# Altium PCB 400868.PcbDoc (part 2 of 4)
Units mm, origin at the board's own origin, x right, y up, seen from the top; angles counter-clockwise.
Board outline 117 x 63.5 mm, 4 copper layers (Top Layer, Mid-Layer 1, Mid-Layer 2, Bottom Layer), stack 1.58 mm thick; 211 components, 153 nets, 878 pads, 1351 vias.
Unrouted connection lines stored in the file: 16.
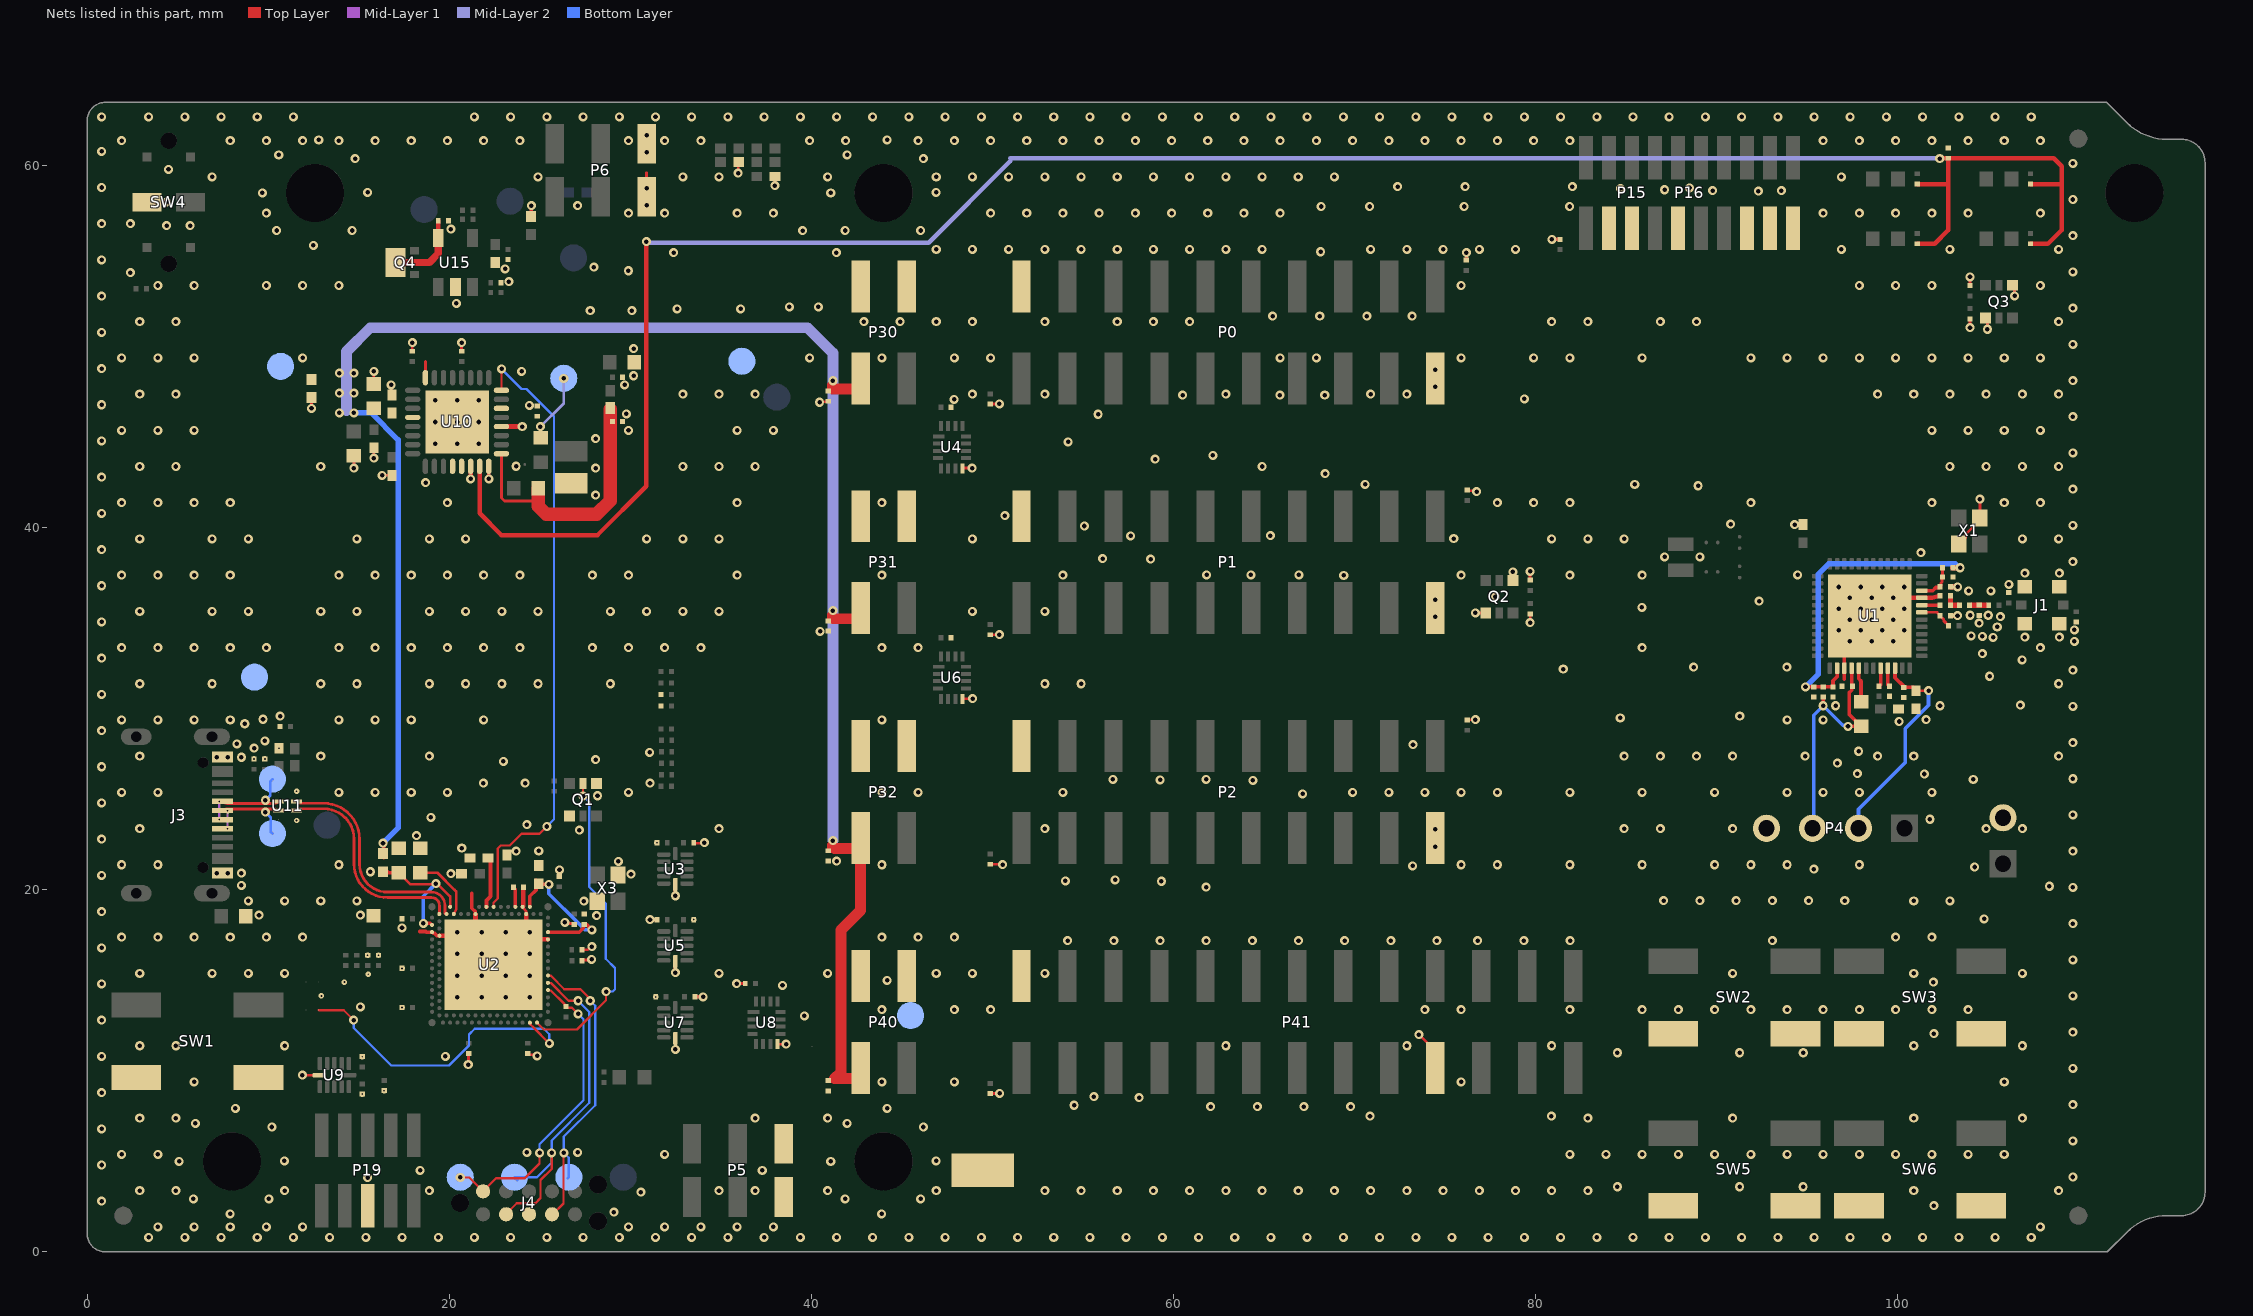
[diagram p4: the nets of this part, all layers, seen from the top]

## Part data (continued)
C10 C14: library part C0201-2µ2-2.5V-X6T-GRM033D80E225ME47D, "Capacitor, Ceramic, 2.2µF 2.5V X6T 0201,±20%", Manufacturer=Murata, Manufacturer Part Number=GRM033D80E225ME47D, Part number IPS=N.A., Part number NEMS=100200527, Supplier Part Number 1=81-GRM033D80E225ME7D
C11: library part C0201-10n-6.3V-X7R, "Capacitor, X7R, 6.3V", Manufacturer=Murata, Manufacturer Part Number=GRM033R70J103KA01D, Part number IPS=N.A., Part number NEMS=100200407, Supplier Part Number 1=490-1262-1-ND
C12: library part C0201-1n0, "Capacitor, X7R, ±10%, 25V", Manufacturer=N.A., Part number IPS=00000003206, Part number NEMS=100200056
C13: library part C0201-3.9p, "Chip Cap 0201", Manufacturer=N.A., Part number NEMS=100200024,100200424
C15 C16 C17 C18 C19 C20 C21 C22 C25 C29 C34 C35 C36 C37 C44 C46 C48 C51 C52 C53 C55 C56 C57 C60 C61 C62 C63 C64 C65 C66 C67 C68 C69 C70 C71 C72 C74 C77 C78 C79 C80 C82: library part C0201-100n, "Capacitor, X5R, ±10%", Manufacturer=N.A., Part number IPS="00000001248, 00000002505", Part number NEMS=100200078, Part number Norautron=262071862
C23: library part C0402-2µ2-10V, "Capacitor, X5R, ±10%", Manufacturer=N.A., Part number NEMS=100200376, Supplier Part Number 1=490-10451-1-ND
C24 C26 C27: library part C0603-10µ-10V-X7T-GRM188D71A106MA73, "Capacitor, X7T, ±20%, 10V", Manufacturer=Murata, Manufacturer Part Number=GRM188D71A106MA73D, Part number IPS=00000004696, Part number NEMS=100200414, Part number Norautron=N.A., Supplier Part Number 1=490-7200-1-ND
C30 C87: library part C0201-10n, "Capacitor, X7R, ±10%", Manufacturer=N.A., Part number IPS=00000003480, Part number NEMS=100200067, Part number Norautron=26621779
C31 C32 C38 C39 C45 C75 C81: library part C0402-1µ0-6.3V-X5R-10%, "Capacitor, X5R, ±10%, 6.3V", Manufacturer=N.A., Part number NEMS=100200498, Part number Norautron=26207137
C33: library part C0201-2n2, "Capacitor, X7R, ±10%, 10V", Manufacturer=N.A., Part number IPS=00000001778, Part number NEMS=100200060, Part number Norautron=26470002
C40: library part C0603-2µ2-6.3V-X7R, "Capacitor, X7R, ±10%, 6.3V", Manufacturer=N.A., Part number NEMS=100200272
C41: library part C0402-100n, "Capacitor, X7R, ±10%", Manufacturer=N.A., Part number IPS=00000005296, Part number NEMS=100200184
C42 C43 C54 C58: library part C0603-4µ7-10V-X7S, "Capacitor, X7S, ±10%, 10V", Manufacturer=N.A., Part number IPS=00000001779, Part number NEMS=100200351, Supplier Part Number 1=445-14258-1-ND
C47: library part C0402-1µ0-16V-X5R, "Capacitor, Ceramic, X5R, ±10%, 16V", Manufacturer=Murata, Manufacturer Part Number=GRT155R61C105KE01D, Part number IPS=N.A., Part number NEMS=100200452, Supplier Part Number 1=490-12255-1-ND
C59: library part C0603-10n-100V-X7R, "Capacitor, X7R, ±10%, 100V", Manufacturer=Murata, Manufacturer Part Number=GCM188R72A103KA37D, Part number IPS=N.A., Part number NEMS=100200349, Supplier Part Number 1=490-4781-1-ND
C73: library part C0201-1p8-50V-COG-GJM0335C1H1R8BB01, "CAP CER 1.8PF 50V C0G/NP0 0201", Manufacturer=Murata, Manufacturer Part Number=GJM0335C1H1R8BB01, Part number IPS=N.A., Part number NEMS=100200681, Supplier Part Number 1=490-17159-1-ND
C76: library part C0402-1µ0-10V-X5R, "Capacitor, Ceramic, X5R, ±10%, 10V", Manufacturer=N.A., Part number NEMS=100200482
FB1 FB2: library part FB0201-120R@100M-200mA-BLM03AG121SN1D, "Ferrite Bead, 120 Ohm @ 100MHz, 200mA, 500 mOhm Max", Manufacturer=Murata, Manufacturer Part Number=BLM03AG121SN1D, Part number IPS=N.A., Part number NEMS=100300419, Supplier Part Number 1=490-5622-1-ND
FB3 FB4: library part FB0402-120R@100M-500mA, "Ferrite Bead, 120 Ohm @ 100MHz, 500mA, 250 mOhm Max", Manufacturer=Murata, Manufacturer Part Number=BLM15AG121SN1D, Part number IPS=00000009954, Part number NEMS=100300099, Part number Norautron=265230631, Supplier Part Number 1=490-1005-1-ND
Fid1 Fid2 Fid3: library part Fid-Mark, "Fiducial Mark", Manufacturer=N.A., Part number NEMS=100500073
J1: "Coaxial Connector with Switch", Manufacturer=Murata, Part number IPS=00000009955, Part number NEMS=100500400, Part number Norautron=26030338, Supplier Part Number 1=490-4981-1-ND
J3: library part 80259-1021, "USB-C Receptacle, 16 Pin, USB 2.0", Manufacturer="Bellweather Electronic Corp.", Part number IPS=N.A., Part number NEMS=100500830
J4: library part TC2050-IDC-NLFP, "CBL PLUG-OF-NAILS 10-PIN", Manufacturer="Tag-Connect LLC", Part number IPS=N.A., Part number NEMS=100500463, Supplier Part Number 1=TC2050-IDC-NL-ND
JP1: library part "SHUNT JUMPER 2.54mm Black Vertical", "Shunt Jumper 2.54mm Black, open top", Manufacturer=WCON, Manufacturer Part Number=3710-6001OS0B05, Part number IPS=N.A., Part number NEMS=100500728
L1: library part L0603-4µ7-MLZ1608M4R7WT000, "Inductor, 120mA, ±20%, 0.65R", Manufacturer="TDK Corporation", Manufacturer Part Number=MLZ1608M4R7WT000, Part number IPS=N.A., Part number NEMS=100300440, Supplier Part Number 1=445-6390-2-ND
L2: library part L0201-2n7-HQ-Murata, "Inductor, 600mA, ±0.1ｎH, 120mOhm", Manufacturer=Murata, Manufacturer Part Number=LQP03HQ2N7B02, Part number IPS=00000001753, Part number NEMS=100300214, Part number Norautron=N.A., Supplier Part Number 1=490-13909-1-ND
L3 L4: library part L0201-3n5-HQ-Murata, "Inductor, 500mA, ±0.1ｎH, 170mOhm", Manufacturer=Murata, Manufacturer Part Number=LQP03HQ3N5B02, Part number IPS=N.A., Part number NEMS=100300222, Supplier Part Number 1=490-13925-1-ND
L8: library part L0806-2µ2-2500mA-73mOhm-CIGT201610EH2R2MNE, "Inductor, Irms=2.5A, Isat=2.9A, ±20%, DCR=73mΩ", Manufacturer="Samsung Electro-Mechanics America", Manufacturer Part Number=CIGT201610EH2R2MNE, Part number IPS=N.A., Part number NEMS=100300400, Part number Norautron=26521789, Supplier Part Number 1=1276-6901-1-ND
LABEL1: library part Label_12x12, "PCA version label, stick-on, 12x12mm", Manufacturer="Ellco Etikett", Manufacturer Part Number=A33512‐01, Part number IPS=N.A., Part number NEMS=101200028
LABEL2: library part Label_20x40, "Early Access Label", Manufacturer=NA, Part number IPS=N.A.
LD1 LD2 LD3 LD4 LD5: library part "VS 25C7M5", "LED, Green, 0603, 573nm, Vf=2.0V, 24mcd, - 40 to +85°C", Manufacturer="Victory Electronics", Part number IPS="00000001274, 00000009961", Part number NEMS=101400097, Part number Norautron=26313411, Supplier Part Number 1=N.A.
LOGO1: library part "Nordic Logo lying", "Nordic logo lying", Manufacturer=N.A., Part number NEMS=101100001
LOGO2: library part "WEEE Symbol 3x4.5mm", "WEEE Directive symbol", Manufacturer=N.A., Part number NEMS=101100006
LOGO3: "Segger logo, small size", Manufacturer=N.A., Part number NEMS=101100004
NT2: library part "2 pin starpoint", "Starpoint", Manufacturer=N.A., Part number NEMS=100500603
P0 P1 P2: library part "Pin Header 2x10 SMD, 2.54mm", "Pin Header 2x10, 2.54mm (100mil) SMD", Manufacturer=WCON, Manufacturer Part Number=1125-1210S0M116CR09, Part number IPS=N.A., Part number NEMS=100500738
P3: "Pin List 1x2, 2.54mm (100mil)", Manufacturer=N.A., Part number NEMS=100500297
P4: "Pin List 1x4, 2.54mm (100mil)", Manufacturer=N.A., Part number NEMS=100500309
P5 P6: library part "Pin List 1x3 SMD", "Pin List 1x3, 2.54mm (100mil), SMD", Manufacturer=WCON, Manufacturer Part Number=1125-1103S0M116CR04, Part number IPS=N.A., Part number NEMS=100500306, Part number Norautron=26470016
P15 P19: library part "Pin Header 2x5 SMD, 1.27mm, KS", "Pin Header 2x5, 1.27mm (50mil), SMD, Keying Shroud", Manufacturer=WCON, Manufacturer Part Number=3132-10MS0BK00R5, Part number IPS=N.A., Part number NEMS=100500261
P16: library part "Pin Header 2x10 SMD, 1.27mm, KS, N.C.", "Pin Header 2x10, 1.27mm (50mil), SMD, Keying Shroud", Manufacturer=WCON, Manufacturer Part Number=3132-20MS0BK00R1, Part number IPS=N.A., Part number NEMS=100500279
P30 P31 P32 P40: "Pin Header 2x2, SMD, 2.54mm (100mil)", Manufacturer=WCON, Manufacturer Part Number=1125-1202S0M116CR03, Part number IPS=N.A., Part number NEMS=100500770
P41: library part "Pin Header 2x13 SMD, 2.54mm", "Pin Header 2x13, 2.54mm (100mil) SMD", Manufacturer=WCON, Manufacturer Part Number=1125-1213S0M116CR09, Part number IPS=N.A., Part number NEMS=100500908
Q1 Q2 Q3: "MOSFET 2N-CH 60V 0.17A TSSOP6 (SOT363)", Manufacturer=Nexperia, Manufacturer Part Number=NX138AKSX, Part number IPS=N.A., Part number NEMS=101300207, Supplier Part Number 1=1727-2732-2-ND
Q4: library part PBSS4330PA,115, "30V, 3A, 2.1W, G=270, NPN Transistor", Manufacturer=Nexperia, Part number IPS=N.A., Part number NEMS=101300184, Supplier Part Number 1=1727-5112-1-ND‎
R1 R36: library part R0201-1k0, "Resistor, ±1%, 0.05W", Manufacturer=N.A., Part number IPS=00000005786, Part number NEMS=100100043
R2: library part R0402-1R0, "Resistor, ±1%, 0.063W", Manufacturer=N.A., Part number IPS=00000004795, Part number NEMS=100100112, Part number Norautron=261080032
R5: library part R0201-560, "Resistor, ±1%, 0.05W", Manufacturer=N.A., Part number IPS=00000007447, Part number NEMS=100100038
R6 R8 R13 R14 R15 R16 R17 R23 R28 R29 R32 R39 R56: library part R0201-100k, "Resistor, ±1%, 0.05W", Manufacturer=N.A., Part number IPS=00000001419, Part number NEMS=100100080, Part number Norautron=26108487
R7: library part R0201-47R, "Resistor, ±1%, 0.05W", Manufacturer=N.A., Part number IPS=00000004794, Part number NEMS=100100022, Part number Norautron=26108300
R10 R11 R12 R18 R27: library part R0201-1M0, "Resistor, ±1%, 0.05W", Manufacturer=N.A., Part number IPS=00000001418, Part number NEMS=100100093, Part number Norautron=26107108
R19 R20 R21 R22: library part R0201-220, "Resistor, ±1%, 0.05W", Manufacturer=N.A., Part number IPS=00000000863, Part number NEMS=100100032, Part number Norautron=26107014
R25 R26 R35: library part R0201-0R, "Resistor, ±5%, 0.05W", Manufacturer=N.A., Part number IPS=00000003245, Part number NEMS=100100001
R40: library part R0402-2R2, "Resistor, ±1%, 0.063W", Manufacturer=N.A., Part number IPS=00000001796, Part number NEMS=100100116, Part number Norautron=26470034
R46 R47: library part R0201-10k, "Resistor, ±1%, 0.05W", Manufacturer=N.A., Part number IPS=00000001255, Part number NEMS=100100065, Part number Norautron=26107101
R48: library part R0201-33k, "Resistor, ±1%, 0.05W", Manufacturer=N.A., Part number IPS=00000001708, Part number NEMS=100100073
R50 R51 R52 R53: library part R0402-0R, "Resistor, ±5%, 0.063W", Manufacturer=N.A., Part number IPS=00000007128, Part number NEMS=100100109, Supplier Part Number 1=146-9661
R54 R55: library part R0402-10k, "Resistor, ±1%, 0.063W", Manufacturer=N.A., Part number IPS=00000002093, Part number NEMS=100100198, Supplier Part Number 1=173-8864
SB1 SB8: Manufacturer=N.A., Part number NEMS=100500458
SB2: library part "Solderbridge Shorted", "Shorted Solderbridge", Manufacturer=N.A., Part number NEMS=100500459
SB3 SB4: library part "Solderbridge Shorted 0.4mm", "Shorted Solderbridge", Manufacturer=N.A., Part number NEMS=100500561
SB5 SB6: library part "Solderbridge 0.4mm", Manufacturer=N.A., Part number NEMS=100500560
SW1 SW2 SW3 SW5 SW6: library part Switch-PB-6.2x6.3mm-SMD, "Tactile Switch, SPNO, SMD, 160gf, 6.2x6.3x2.5mm", Manufacturer=Dailywell, Manufacturer Part Number=TS604VM1-025BR-R, Part number IPS=00000007812, Part number NEMS="101500001, 101500133", Part number Norautron=N.A.
SW4: library part Switch-Slide-RA-J-Lead-DPDT-8.5x3.5mm_C&K, "SMD slide Switch (ON-ON)", Manufacturer=C&K, Manufacturer Part Number=JS202011JAQN, Part number IPS=00000007811, Part number NEMS=101500037, Part number Norautron=N.A., Supplier Part Number 1=CKN10722CT-ND
TP1 TP3 TP4 TP5 TP6 TP8 TP9 TP10 TP11 TP12 TP13 TP14 TP15 TP16 TP17 TP18: library part TP_SMD_Ø1.5MM, "1.5mm circular SMD testpad", Manufacturer="Nordic Semiconductor", Manufacturer Part Number=N.A., Part number NEMS=100500477
TP22: library part "TP - S1751-46R", "PC TEST POINT TIN SMD L", Manufacturer=Harwin, Manufacturer Part Number=S1751-46R, Part number IPS=N.A., Part number NEMS=100500525, Supplier Part Number 1=952-1478-1-ND
U1: "Multi-protocol Bluetooth Low Energy, IEEE 802.15.4 and 2.4GHz proprietary Wireless MCU", Manufacturer="Nordic Semiconductor", Part number IPS=N.A., Part number NEMS=102000385
U2: "Multi-protocol Bluetooth Low Energy, IEEE 802.15.4, ANT and 2.4GHz proprietary system-on-chip", Manufacturer="Nordic Semiconductor", Part number IPS=N.A., Part number NEMS=102000153
U3 U5: library part TXU0204RUTR, "4-Bit Fixed Direction Voltage-Level Translator with Schmitt-Trigger Inputs and 3-State Outputs", Manufacturer="Texas Instruments", Part number IPS=N.A., Part number NEMS=101900849, Supplier Part Number 1=296-TXU0204RUTR-ND
U4 U6 U8: "Low-Capacitance, 1:1 (SPST) 4-Channel, analog switch", Manufacturer="Texas Instruments", Manufacturer Part Number=TMUX1511RSVR, Part number IPS=N.A., Part number NEMS=101900847, Supplier Part Number 1=296-53443-2-ND
U7: library part TXB0304RUTR, "4-Bit Bidirectional Level-Shifter/Voltage Translator with Automatic Direction Sensing", Manufacturer="Texas Instruments", Part number IPS=N.A., Part number NEMS=101900199, Supplier Part Number 1=296-29682-1-ND
U9: library part TXB0104RUTR, "4-Bit Bidirectional Level-Shifter/Voltage Translator with Automatic Direction Sensing", Manufacturer="Texas Instruments", Part number IPS=N.A., Part number NEMS=101900856, Supplier Part Number 1=296-25888-2-ND
U10: "Li-Ion/Li-Polymer USB-C battery charger with high efficiency buck regulators, LDOs or load switches, LED drivers, TWI and VBUSOUT", Manufacturer="Nordic Semiconductor", Part number IPS=N.A., Part number NEMS=102000291
U11: "2 Line Common mode filter with ESD protection for USB 2.0 interface", Manufacturer=STMicroelectronics, Part number IPS=N.A., Part number NEMS=100800034, Supplier Part Number 1=497-13420-2-ND
U15: library part TLV271CW5-7, "Dual rail to rail CMOS Amplifier", Manufacturer="Diodes Incorporated", Part number IPS=N.A., Part number NEMS=101900398, Supplier Part Number 1=TLV271CW5-7DICT-ND
X1: library part XTAL_SMD2016_32MHz_8pF_Kyocera, "XTAL SMD 2016, 32MHz, Cl=8pF, Tot: ±40ppm", Manufacturer=Kyocera, Manufacturer Part Number=CX2016DB32000D0WZRC1, Part number IPS=00000007827, Part number NEMS=101600039, Part number Norautron=26511136, Supplier Part Number 1=1253-1586-1-ND
X2: library part XTAL_SMD2012_32.768kHz_9pF_TXC, "XTAL SMD 2012, 32.768kHz, 9pF, ±20ppm", Manufacturer="TXC Corporation", Manufacturer Part Number=9HT11-32.768KDZC-T, Part number IPS=N.A., Part number NEMS=101600107, Supplier Part Number 1=887-1426-2-ND
X3: library part XTAL_SMD2016_32MHz_8pF_Golledge, "XTAL SMD 2016, 32MHz, Cl=8pF, Tol: ±10ppm, Stab: ±15ppm", Manufacturer=Golledge, Manufacturer Part Number=MP06003, Part number IPS=00000001431, Part number NEMS=101600041,101600118, Part number Norautron=N.A.

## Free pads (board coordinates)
  round 3.2 hole 3.2 unplated: 1(8.004,5) 1(12.604,58.5) 1(44.004,5) 1(44.004,58.5) 1(113.104,58.5)

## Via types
v1: diameter 0.5, hole 0.25, Top Layer to Bottom Layer, tented both sides, 1252 vias
v2: diameter 0.3, hole 0.1, Top Layer to Mid-Layer 1, tented top, 72 vias
v3: diameter 0.3, hole 0.1, Top Layer to Mid-Layer 1, tented both sides, 18 vias
v4: diameter 0.5, hole 0.25, Top Layer to Bottom Layer, tented bottom, 9 vias

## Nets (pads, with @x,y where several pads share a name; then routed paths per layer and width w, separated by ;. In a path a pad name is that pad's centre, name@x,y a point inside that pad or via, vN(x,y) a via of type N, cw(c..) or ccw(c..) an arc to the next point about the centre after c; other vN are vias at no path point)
5V0: C24.2 C26.2 C55.2 C56.2 C60.2 C63.2 C74.2 C75.2 C78.1 P30.1 P31.1 P32.1 P40.1 Q4.3 R40.2 R55.2 TP10.1 U10.4 U10.20 U10.30 U10.32 U15.5 | length 120.3
  Top Layer w0.15: U10.32@22.192,43.396 U10.32@22.196,43.392 ; v1@22.196,42.704 v1(22.2,42.7)
  Top Layer w0.2: v1(16.35,22.587) 16.392,22.545 R40.2@16.392,21.787 ; v1@22.196,42.704 U10.32@22.196,43.392 ; C63.2@40.95,22.16 C63.2@40.965,22.16 ; C60.2@40.965,34.86 40.965,35.19 v1(41.2,35.425) ; C55.2@40.965,47.56 40.965,47.89 v1(41.2,48.125) ; 41.143,22.353 41,22.21 41,22.195 C63.2@40.965,22.16 ; v1(41.2,22.725) 40.965,22.49 C63.2@40.965,22.16
  Top Layer w0.25: v1(21.192,42.7) U10.30@21.192,43.396
  Top Layer w0.27: U15.5@19.4,56 C78.1@19.4,56.975 ; C74.2@40.95,9.46 P40.1@42.361,9.46 ; C63.2@40.95,22.16 P32.1@42.361,22.16 ; P31.1@42.734,34.663 P31.1@42.734,35.56 ; P30.1@42.75,46.99 P30.1@42.75,47.75
  Top Layer w0.3: U10.4@22.892,45.596 v1@24.038,45.596
  Top Layer w0.4: Q4.3@17.05,54.65 18.9,54.65 19.4,55.15 U15.5@19.4,56
  Top Layer w0.6: 41.225,34.975 P31.1@42.6,34.975 ; 41.225,47.675 P30.1@42.6,47.675 ; 41.299,22.275 P32.1@42.6,22.275 ; P40.1@42.6,9.575 41.299,9.575 41.65,9.926 41.65,17.775 42.734,18.859 42.734,22.368 P32.1@42.759,22.393
  Mid-Layer 2 w0.15: v1(25.042,45.596) 25.061,45.596 26.334,46.869 v1(26.334,48.26)
  Mid-Layer 2 w0.6: 14.342,46.479 14.342,49.746 15.646,51.05 39.8,51.05 41.2,49.65 v1(41.2,48.125) v1(41.2,35.425) v1(41.2,22.725)
  Bottom Layer w0.3: v1(14.742,46.346) 15.704,46.346 17.192,44.858 17.192,23.429 v1(16.35,22.587)
  other v1: 24.042,45.596 13.942,46.346 13.942,47.446 14.742,47.446 13.942,48.546 14.742,48.546
ANT: L2.1 U1.32 | length 0.9
  Top Layer w0.2: U1.32@101.505,35.73 L2.1@102.364,35.73
CFLYH: C3.2 U1.21 | length 0.9
  Top Layer w0.125: C3.2@99.565,31.222 C3.2@99.565,31.237
  Top Layer w0.2: U1.21@99.48,32.105 99.48,31.34 C3.2@99.565,31.255
CFLYL: C3.1 U1.20 | length 1
  Top Layer w0.125: C3.1@99.004,31.237 99.004,31.214 C3.1@99.068,31.15
  Top Layer w0.2: C3.1@98.995,31.24 98.995,31.255 99.08,31.34 U1.20@99.08,32.105
D_N: J3.A7 J3.B7 TP17.1 U11.2 | length 5.5
  Top Layer w0.153: J3.B7@7.489,24.875 ccw(c7.727,25.113) 7.727,24.777 10.322,24.777 ccw(c10.322,25.141) U11.2@10.579,24.883
  Mid-Layer 1 w0.127: v2(7.3,23.881) v2(7.3,24.884)
  Bottom Layer w0.153: v1(9.85,24.95) 10.125,25.225 10.125,26 TP17.1@10.241,26.115
D_P: J3.A6 J3.B6 TP18.1 U11.3 | length 5.5
  Top Layer w0.153: J3.A6@7.489,24.375 cw(c7.727,24.137) 7.727,24.474 10.361,24.474 cw(c10.361,24.165) U11.3@10.579,24.383
  Mid-Layer 1 w0.127: v2(7.763,23.371) v2(7.763,24.374)
  Bottom Layer w0.153: v1(9.85,24.3) 10.147,24.003 10.147,23.206 TP18.1@10.241,23.113
DBGR_BUTTON: SB2.2 U2.AL27 | length 17.7
  Top Layer w0.125: SB2.2@12.8,13.364 12.815,13.35 14.179,13.35 v1(14.729,12.8) ; U2.AL27@24.46,12.664 24.46,12.637 24.51,12.587 24.51,12.555 24.631,12.434 24.631,12.427 v1(25.54,11.518)
  Top Layer w0.15: U2.AL27@24.46,12.622 U2.AL27@24.46,12.637
  Bottom Layer w0.125: v1(14.729,12.8) 14.729,12.371 16.8,10.3 20,10.3 20.913,11.213 21.1,11.4 21.1,12.009 21.416,12.325 25.245,12.325 25.54,12.03 v1(25.54,11.518)
DBGR_LED: Q1.2 U2.AL29 | length 17.6
  Top Layer w0.125: U2.AL29@24.86,12.664 25.237,12.288 27.066,12.288 28.675,13.897 v1(28.675,14.381) ; v1(27.401,25.175) Q1.2@27.401,25.71
  Bottom Layer w0.125: v1(27.401,25.175) 27.738,24.838 27.738,20.162 28.65,19.25 28.65,16.2 29.162,15.688 29.162,14.512 29.037,14.387 28.682,14.387 v1(28.675,14.381)
DBGR_N: U2.B4 U11.7 | length 12.6
  Top Layer w0.153: U11.7@11.579,24.883 ccw(c11.833,25.137) 11.833,24.778 11.879,24.778 13.05,24.778 13.084,24.778 cw(c13.084,22.81) 15.053,22.81 15.053,21.422 ccw(c16.6,21.422) 16.6,19.875 19.033,19.875 cw(c19.033,19.138) 19.77,19.138 19.77,18.755 ccw(c19.86,18.755) U2.B4@19.86,18.664
DBGR_P: U2.B2 U11.6 | length 12
  Top Layer w0.153: U11.6@11.579,24.383 cw(c11.801,24.161) 11.801,24.475 11.879,24.475 13.05,24.475 13.084,24.475 cw(c13.084,22.81) 14.75,22.81 14.75,21.422 ccw(c16.6,21.422) 16.6,19.572 19.033,19.572 cw(c19.033,19.138) 19.467,19.138 19.467,18.664 U2.B2@19.46,18.664
DBGR_RESET: J4.10 R6.1 TP4.1 U2.AC31 | length 17
  Top Layer w0.125: v1(20.616,4.115) 21.108,4.115 J4.10@21.878,3.344 22.609,4.075 24.201,4.075 25.001,4.876 v1(25.001,5.475) ; U2.AC31@25.46,14.464 25.479,14.445 25.616,14.445 26.372,13.689 26.372,13.628 26.517,13.483 26.792,13.483 v1(27.125,13.15)
  Bottom Layer w0.125: v1(25.001,5.475) 25.001,5.945 27.429,8.372 27.429,11.667 27.429,12.847 v1(27.125,13.15)
DBGR_SWDCLK: J4.4 TP6.1 U2.W31 | length 17.4
  Top Layer w0.125: U2.W31@25.46,15.264 25.471,15.254 25.624,15.254 26.363,14.515 27.26,14.515 27.8,13.975 v1(27.8,13.875) ; J4.4@25.688,2.074 25.724,2.074 26.324,2.674 26.324,5.459 v1(26.34,5.475)
  Bottom Layer w0.125: TP6.1@26.559,4.067 TP6.1@26.564,4.062 ; TP6.1@26.616,4.125 26.616,5.198 v1(26.34,5.475) 26.34,6.373 28.072,8.106 28.072,13.603 v1(27.8,13.875)
DBGR_SWDIO: J4.2 TP5.1 U2.AA31 | length 19.8
  Top Layer w0.125: J4.2@23.148,2.074 23.148,2.099 23.74,2.69 24.771,2.69 25.053,2.972 25.053,3.968 25.667,4.582 v1(25.667,5.475) ; U2.AA31@25.46,14.864 25.471,14.854 25.624,14.854 26.603,13.875 v1(27.125,13.875)
  Bottom Layer w0.125: TP5.1@23.616,4.125 24.851,4.125 25.667,4.94 25.667,6.158 27.749,8.24 27.749,13.252 v1(27.125,13.875)
  Bottom Layer w0.15: TP5.1@23.616,4.115 TP5.1@23.759,3.972
DCC: L1.1 U1.17 | length 1.8
  Top Layer w0.2: U1.17@97.88,32.105 97.88,31.655 98.001,31.534 L1.1@98.001,30.385
DECA: C10.2 C11.2 FB1.2 FB2.2 U1.14 | length 17.6
  Top Layer w0.203: v1(94.933,31.215) C10.2@95.377,31.215 96.452,31.215 96.452,31.554 96.68,31.783 U1.14@96.68,32.105
  Top Layer w0.3: FB2.2@103.072,37.795 v1(103.474,37.795)
  Bottom Layer w0.3: v1(94.933,31.215) 95.638,31.92 95.638,37.437 96.222,38.021 103.198,38.021 103.424,37.795 v1(103.474,37.795)
DECB: C4.2 C5.1 P4.2 U1.22 | length 11.7
  Top Layer w0.125: C4.2@101.048,31.003 v1(101.73,31.003)
  Top Layer w0.2: U1.22@99.88,32.105 99.88,31.721 C5.1@100.371,31.23 ; C5.1@100.388,31.194 100.898,31.194 101.048,31.044 C4.2@101.048,31.003
  Bottom Layer w0.2: P4.2@97.86,23.4 97.86,24.46 100.437,27.037 100.437,28.909 101.73,30.202 v1(101.73,31.003)
DECD: C6.2 FB1.1 L1.2 P4.3 U1.16 | length 13.5
  Top Layer w0.2: v1(95.91,30.17) FB1.1@95.91,30.645 ; v1(97.28,29.035) 97.909,29.035 L1.2@98.001,28.943 ; U1.16@97.48,32.105 97.48,31.028 97.341,30.888 97.341,29.702 97.998,29.045 L1.2@98.001,29.045
  Bottom Layer w0.2: P4.3@95.32,23.4 95.387,23.467 95.387,29.646 v1(95.91,30.17) 96.988,29.092 97.213,29.092 97.275,29.03 v1(97.28,29.035) ; v1@95.895,30.123 v1@95.895,30.17
DECRF: C12.2 C14.2 FB2.1 U1.34 | length 2
  Top Layer w0.15: C12.2@102.363,36.745 102.423,36.805 102.423,36.956 102.474,37.006 102.474,37.254 C14.2@102.501,37.282 FB2.1@102.502,37.795
  Top Layer w0.2: U1.34@101.505,36.53 101.968,36.53 102.138,36.7 C12.2@102.328,36.7
GND: C1.1 C2.1 C4.1 C5.2 C6.1 C7.1 C8.1 C9.1 C10.1 C11.1 C12.1 C13.1 C14.1 C15.1 C16.2 C17.2 C18.2 C19.2 C20.2 C21.2 C22.2 C23.1 C25.1 C26.1 C29.2 C30.2 C31.2 C32.1 C33.2 C34.2 C35.2 C36.2 C37.2 C38.1 C39.1 C40.2 C41.1 C42.2 C43.2 C44.2 C45.1 C46.1 C47.1 C48.1 C51.1 C52.1 C53.1 C54.2 C55.1 C56.1 C57.1 C58.2 C59.2 C60.1 C61.1 C62.1 C63.1 C64.1 C65.1 C66.1 C67.2 C68.1 C69.2 C70.2 C71.2 C72.1 C73.1 C74.1 C75.1 C76.1 C77.1 C78.2 C79.1 C80.2 C81.1 C82.2 C87.2 J1.2 J3.A1 J3.A12 J4.3 NT2.1 P0.2 P0.19 P1.2 P1.19 P2.2 P2.19 P3.2 P4.4 P5.1 P6.1 P15.3 P15.5 P15.9 P16.3 P16.5 P16.9 P16.15 P16.17 P16.19 P19.5 P30.2 P30.4 P31.2 P31.4 P32.2 P32.4 P40.2 P40.4 P41.2 P41.19 Q1.1 Q1.4 Q2.1 Q2.4 Q3.1 Q3.4 R7.2 R10.2 R11.2 R12.2 R18.1 R26.2 R27.2 R32.2 R47.1 R53.2 R54.1 R55.1 R56.2 SW1.1 SW2.1 SW3.1 SW4.2 SW5.1 SW6.1 TP12.1 TP13.1 TP14.1 TP15.1 TP22.1 U1.15 U1.33 U1.49 U2.104 U2.A25 U2.B12 U2.B26 U2.G1 U2.H2 U2.J31 U3.6 U4.8 U5.6 U6.8 U7.6 U8.8 U9.6 U10.6 U10.16 U10.28 U10.29 U10.33 U11.5 U11.8 U15.2 X1.2 X1.4 X3.2 X3.4 | length 52
  Top Layer w0.15: v1(11.9,9.765) U9.6@12.639,9.765 ; v1(12.4,46.6) R55.1@12.4,47.2 ; v1(14.742,43.3) C54.2@14.742,43.971 ; v1(15.842,43.85) C23.1@15.842,44.421 ; C26.1@15.842,47.946 v1(15.842,48.646) ; v1(16.3,42.9) 16.838,42.9 C76.1@16.842,42.896 ; v1(16.8,47.9) 16.8,47.173 C75.1@16.804,47.169 ; R26.2@17.973,49.753 v1(17.973,50.228) ; U10.16@18.678,48.31 U10.16@18.692,48.296 18.692,49.183 ; v4(20.442,45.846) U10.33@21.192,46.596 ; C29.2@20.692,49.753 v1(20.692,50.228) ; v1(21.06,10.35) 21.076,10.366 21.076,10.938 C22.2@21.092,10.954 ; U2.A25@24.06,19.064 24.06,19.044 24.148,18.957 24.148,18.935 24.246,18.837 24.246,18.679 U2.B26@24.26,18.664 ; C34.2@24.344,10.954 24.404,10.894 24.697,10.894 24.766,10.825 v1(24.86,10.825) ; v1(26.4,18.2) 26.454,18.146 26.854,18.146 C36.2@26.909,18.091 ; R7.2@27.345,16.687 27.636,16.687 27.814,16.864 v1(27.885,16.864) ; C35.2@27.353,16.078 27.395,16.12 27.831,16.12 v1(27.873,16.162) ; P6.1@30.912,58.666 30.912,59.141 30.912,59.616 ; P6.1@30.912,61.596 P6.1@30.912,62.071 ; v1(32.5,11.188) U7.6@32.5,11.8 ; C16.2@33.545,22.577 v1@34.073,22.577 ; v1(35.885,14.825) C71.2@36.36,14.825 ; v1(35.97,59.6) 35.97,60.17 R53.2@36,60.2 ; v1(38,58.9) v1@38,58.972 ; U8.8@38.145,11.475 v1(38.62,11.475) ; v1(40.467,46.938) 40.493,46.964 40.924,46.964 C55.1@40.95,46.99 ; P32.2@42.734,27.465 P32.2@42.734,27.94 P32.2@42.734,28.415 ; P31.2@42.734,40.165 P31.2@42.734,40.64 P31.2@42.734,41.115 ; P32.4@45.274,27.465 P32.4@45.274,27.94 P32.4@45.274,28.415 ; P31.4@45.274,40.165 P31.4@45.274,40.64 P31.4@45.274,41.115 ; U6.8@48.361,30.561 v1(48.925,30.561) ; U4.8@48.375,43.275 48.4,43.3 v1(48.9,43.3) ; C61.1@49.9,34.09 49.905,34.095 50.395,34.095 v1(50.4,34.1) ; C64.1@49.905,21.42 49.917,21.408 50.567,21.408 v1(50.575,21.4) ; C51.1@49.905,46.836 v1@50.395,46.836 ; C79.1@49.918,8.749 v1@50.408,8.749 ; v1@73.571,12 P41.19@74.484,11.087 ; v1(74.484,22.385) v1(74.484,23.335) ; v1(74.484,35.085) v1(74.484,36.035) ; v1(74.484,47.785) P0.19@74.484,48.26 v1(74.484,48.735) ; C52.1@76.2,54.785 v1(76.2,55.2) ; C65.1@76.25,29.385 76.257,29.392 76.692,29.392 v1(76.7,29.4) ; C62.1@76.25,42.085 76.292,42.042 76.72,42.042 v1(76.762,42) ; v1(76.7,35.3) 77.256,35.3 Q2.4@77.267,35.289 ; Q2.1@78.767,37.089 v1(78.767,37.564) ; R10.2@79.719,37.113 v1(79.719,37.588) ; v1(79.725,34.765) R12.2@79.725,35.24 ; v1(94.329,40.175) C41.1@94.804,40.175 ; X1.4@103.418,39.109 103.768,39.459 103.768,39.626 104.218,40.076 104.218,40.209 X1.2@104.568,40.559 ; v1(104.02,51.065) R27.2@104.02,51.54 ; R11.2@104.02,53.389 v1(104.02,53.864) ; X1.2@104.568,40.534 X1.2@104.568,40.559 ; v1(104.568,41.587) X1.2@104.568,40.559 ; v1(104.982,50.97) Q3.4@104.982,51.6 ; v1(106.482,52.819) Q3.1@106.482,53.4
  Top Layer w0.2: 18.39,17.7 18.711,17.7 18.747,17.664 19.067,17.664 19.13,17.602 19.2,17.602 19.333,17.469 19.456,17.469 U2.H2@19.46,17.464 ; 21.26,19.809 21.26,18.987 21.456,18.792 21.456,18.669 U2.B12@21.46,18.664 ; R54.1@24.525,57.2 24.537,57.212 24.537,57.788 v1(24.549,57.8) ; v1(31.1,18.354) C66.1@31.479,18.354 ; v1(32.5,15.425) U5.6@32.5,16.05 ; v1(32.5,19.675) U3.6@32.5,20.3 ; C69.2@33.585,14.085 v1(34.035,14.085) ; v1(38,58.9) C38.1@38,59.4 ; v1(80.922,55.935) C72.1@81.372,55.935 ; 97.08,31.643 97.08,32.105 U1.49@97.08,33.33
  Top Layer w0.25: U2.H2@19.46,17.464 20.26,17.464 v1(20.46,17.664) ; U2.B12@21.46,18.664 21.46,17.998 v1(21.794,17.664) ; U2.A25@24.06,19.064 24.098,19.102 24.098,19.215 24.11,19.227 24.11,20.129 24.121,20.139 C44.2@24.121,20.154 ; U2.B26@24.26,18.664 24.26,17.864 v1(24.46,17.664) 24.86,17.264 U2.J31@25.46,17.264 ; U1.49@100.284,36.13 101.505,36.13 101.935,36.13 C7.1@102.362,36.244 ; v1(102.364,30.17) v1@102.364,30.217 ; C13.1@102.933,35.144 v1(103.33,35.144)
  Top Layer w0.3: C12.1@102.959,36.745 v1@103.329,36.745
  other v1: 3.404,0.8 5.404,0.8 7.404,0.8 9.404,0.8 11.404,0.8 13.404,0.8 15.404,0.8 17.404,0.8 19.404,0.8 21.404,0.8 23.404,0.8 25.404,0.8 27.404,0.8 29.404,0.8 31.404,0.8 33.404,0.8 35.404,0.8 37.404,0.8 39.404,0.8 41.404,0.8 43.404,0.8 45.404,0.8 47.404,0.8 49.404,0.8 51.404,0.8 53.404,0.8 55.404,0.8 57.404,0.8 59.404,0.8 61.404,0.8 63.404,0.8 65.404,0.8 67.404,0.8 69.404,0.8 71.404,0.8 73.404,0.8 75.403,0.8 77.403,0.8 79.403,0.8 81.403,0.8 83.403,0.8 85.403,0.8 87.403,0.8 89.403,0.8 91.403,0.8 93.403,0.8 95.403,0.8 97.403,0.8 99.403,0.8 101.403,0.8 103.403,0.8 105.403,0.8 107.403,0.8 3.912,1.387 5.912,1.387 7.912,1.387 9.912,1.387 11.912,1.387 29.912,1.387 31.912,1.387 33.912,1.387 35.912,1.387 37.912,1.387 107.912,1.387 7.9,2.1 43.9,2.1 29.1,2.2 102.029,2.558 0.8,2.8 5.875,2.925 10.046,2.925 41.875,2.925 46.046,2.925 30.6,3.3 2.912,3.387 4.912,3.387 10.912,3.387 18.912,3.387 34.912,3.387 36.912,3.387 40.912,3.387 46.912,3.387 52.912,3.387 54.912,3.387 56.912,3.387 58.912,3.387 60.912,3.387 62.912,3.387 64.912,3.387 66.912,3.387 68.912,3.387 70.912,3.387 72.912,3.387 74.912,3.387 76.912,3.387 78.912,3.387 80.912,3.387 82.912,3.387 100.912,3.387 108.912,3.387 84.543,3.6 91.293,3.6 94.804,3.6 15.5,4.1 109.7,4.137 18.4,4.5 37.3,4.5 0.8,4.8 5.084,5 41.084,5 10.905,5.025 46.905,5.025 1.912,5.387 3.912,5.387 31.912,5.387 81.912,5.387 83.912,5.387 85.912,5.387 87.912,5.387 89.912,5.387 91.912,5.387 93.912,5.387 95.912,5.387 97.912,5.387 99.912,5.387 101.912,5.387 103.912,5.387 105.912,5.387 24.3,5.5 27.1,5.5 109.7,6.137 0.8,6.8 10.208,6.9 46.208,6.9 5.99,7.1 41.99,7.1 2.912,7.387 4.912,7.387 36.912,7.387 40.912,7.387 82.912,7.387 90.912,7.387 100.912,7.387 106.912,7.387 70.875,7.5 80.9,7.5 8.2,7.925 44.2,7.925 62.075,8.025 64.65,8.025 67.225,8.025 69.8,8.025 54.525,8.1 109.7,8.137 58.125,8.525 55.625,8.575 50.413,8.754 0.8,8.8 5.912,9.387 43.912,9.387 47.912,9.387 75.912,9.387 105.912,9.387 109.7,10.137 0.8,10.8 19.8,10.8 84.543,11 91.293,11 94.809,11 2.912,11.387 4.912,11.387 10.912,11.387 62.912,11.387 72.912,11.387 80.912,11.387 100.912,11.387 106.912,11.387 73.57,12 102.029,12.058 109.7,12.137 0.8,12.8 39.634,13.038 43.912,13.387 47.912,13.387 49.912,13.387 73.912,13.387 75.912,13.387 81.912,13.387 85.912,13.387 87.912,13.387 89.912,13.387 91.912,13.387 93.912,13.387 95.912,13.387 97.912,13.387 99.912,13.387 101.912,13.387 103.912,13.387 15.1,13.535 20.46,14.064 21.794,14.064 23.127,14.064 24.46,14.064 109.7,14.137 38.42,14.725 0.8,14.8 102,14.9 44.2,15 20.46,15.264 21.794,15.264 23.127,15.264 24.46,15.264 2.912,15.387 6.912,15.387 8.912,15.387 10.912,15.387 34.912,15.387 40.912,15.387 46.912,15.387 48.912,15.387 52.912,15.387 90.912,15.387 100.912,15.387 106.912,15.387 109.7,16.137 20.46,16.464 21.794,16.464 23.127,16.464 24.46,16.464 0.8,16.8 54.175,17.2 56.725,17.2 59.275,17.2 61.825,17.2 64.375,17.2 66.925,17.2 69.475,17.2 72.025,17.2 74.575,17.2 76.825,17.2 79.375,17.2 81.925,17.2 93.1,17.2 1.912,17.387 3.912,17.387 5.912,17.387 7.912,17.387 9.912,17.387 11.912,17.387 43.912,17.387 45.912,17.387 47.912,17.387 99.912,17.387 101.912,17.387 23.127,17.664 17.4,17.9 109.7,18.137 104.8,18.4 28.15,18.575 9.5,18.6 15.1,18.6 0.8,18.8 27.45,19.375 8.912,19.387 10.912,19.387 12.912,19.387 14.912,19.387 87.1,19.4 89.1,19.4 91.1,19.4 93.1,19.4 95.1,19.4 97.1,19.4 100.912,19.387 102.912,19.387 109.7,20.137 61.825,20.15 108.4,20.2 8.529,20.25 59.35,20.475 54.05,20.5 56.8,20.55 0.8,20.8 30.05,20.875 20.1,20.9 7.168,20.921 7.779,20.925 8.529,20.925 15.65,21 26.1,21.1 95.4,21.15 104.277,21.262 73.225,21.325 1.912,21.387 3.912,21.387 13.912,21.387 43.912,21.387 75.912,21.387 77.912,21.387 81.912,21.387 85.912,21.387 89.912,21.387 91.912,21.387 93.912,21.387 97.912,21.387 29.35,21.575 41.404,21.59 23.7,22.138 109.7,22.137 24.953,22.15 20.7,22.3 34.1,22.604 0.8,22.8 18.2,23 27.2,23.3 2.912,23.387 34.912,23.387 52.912,23.387 84.912,23.387 86.912,23.387 90.912,23.387 104.912,23.387 106.912,23.387 24.3,23.6 101.8,23.9 19,24 109.7,24.137 0.8,24.8 28.2,25.2 67.15,25.3 1.912,25.387 3.912,25.387 13.912,25.387 15.912,25.387 17.912,25.387 19.912,25.387 29.912,25.387 43.912,25.387 45.912,25.387 53.912,25.387 69.912,25.387 71.912,25.387 73.912,25.387 75.912,25.387 77.912,25.387 81.912,25.387 85.912,25.387 89.912,25.387 93.912,25.387 95.912,25.387 97.912,25.387 101.912,25.387 21.9,25.9 24.2,25.9 31.1,25.9 64.4,26.05 59.275,26.075 56.675,26.1 61.825,26.1 104.2,26.1 109.7,26.137 101.5,26.4 97.8,26.425 0.8,26.8 96.7,27 23,27.1 28.1,27.2 7.171,27.325 7.779,27.325 8.529,27.325 2.912,27.387 12.912,27.387 18.912,27.387 84.912,27.387 86.912,27.387 88.912,27.387 90.912,27.387 94.912,27.387 98.912,27.387 100.912,27.387 108.912,27.387 31.075,27.6 97.873,27.658 9.225,27.825 73.25,28.025 8.284,28.065 109.7,28.137 9.824,28.225 0.8,28.8 8.713,29.175 100.1,29.3 1.912,29.387 3.912,29.387 5.912,29.387 7.912,29.387 13.912,29.387 15.912,29.387 17.912,29.387 21.912,29.387 43.912,29.387 93.912,29.387 95.912,29.387 101.6,29.4 9.721,29.425 84.7,29.5 10.662,29.6 91.3,29.6 109.7,30.137 96.601,30.17 106.8,30.2 0.8,30.8 2.912,31.387 6.912,31.387 12.912,31.387 14.912,31.387 18.912,31.387 20.912,31.387 22.912,31.387 24.912,31.387 28.912,31.387 52.912,31.387 54.912,31.387 108.912,31.387 105.1,31.8 109.7,32.137 81.55,32.2 88.75,32.3 93.9,32.3 106.9,32.7 0.8,32.8 104.7,33.05 1.912,33.387 3.912,33.387 5.912,33.387 7.912,33.387 9.912,33.387 13.912,33.387 15.912,33.387 17.912,33.387 19.912,33.387 21.912,33.387 23.912,33.387 27.912,33.387 29.912,33.387 31.912,33.387 33.912,33.387 43.912,33.387 45.912,33.387 85.912,33.387 107.912,33.387 97.38,33.73 98.58,33.73 99.78,33.73 109.788,33.73 105.298,33.95 107.055,33.96 108.955,33.96 104.7,34 104.08,34.03 40.493,34.275 96.78,34.33 97.98,34.33 99.18,34.33 100.38,34.33 109.79,34.36 105.525,34.525 104.527,34.741 0.8,34.8 97.38,34.93 98.58,34.93 99.78,34.93 105.7,35.1 104.025,35.17 105.029,35.17 2.912,35.387 6.912,35.387 8.912,35.387 12.912,35.387 14.912,35.387 18.912,35.387 20.912,35.387 22.912,35.387 24.912,35.387 28.912,35.387 30.912,35.387 32.912,35.387 34.912,35.387 48.912,35.387 52.912,35.387 96.78,35.53 97.98,35.53 99.18,35.53 100.38,35.53 85.9,35.6 92.375,35.95 97.38,36.13 98.58,36.13 99.78,36.13 77.8,36.2 103.943,36.52 105.175,36.52 96.78,36.73 97.98,36.73 99.18,36.73 100.38,36.73 103.334,36.74 0.8,36.8 106.166,36.875 1.912,37.387 3.912,37.387 5.912,37.387 7.912,37.387 13.912,37.387 15.912,37.387 17.912,37.387 19.912,37.387 21.912,37.387 23.912,37.387 27.912,37.387 29.912,37.387 35.912,37.387 43.912,37.387 53.912,37.387 69.425,37.375 75.912,37.387 81.912,37.387 85.912,37.387 61.85,37.4 64.3,37.4 66.95,37.4 94.5,37.4 107.055,37.5 108.955,37.5 109.7,38.137 58.75,38.275 56.1,38.3 87.15,38.4 89.1,38.4 101.305,38.63 0.8,38.8 2.912,39.387 6.912,39.387 8.912,39.387 14.912,39.387 18.912,39.387 20.912,39.387 30.912,39.387 32.912,39.387 34.912,39.387 48.912,39.387 80.912,39.387 82.912,39.387 84.912,39.387 106.912,39.387 108.912,39.387 75.5,39.4 57.65,39.55 65.375,39.575 55.1,40.1 109.7,40.137 90.8,40.2 50.7,40.676 0.8,40.8 1.912,41.387 3.912,41.387 5.912,41.387 7.912,41.387 19.912,41.387 35.912,41.387 43.912,41.387 77.912,41.387 79.912,41.387 81.912,41.387 91.912,41.387 101.912,41.387 105.912,41.387 107.912,41.387 28.1,41.807 109.7,42.137 88.995,42.324 70.6,42.4 85.5,42.4 18.7,42.5 0.8,42.8 68.4,43 28.1,43.3 2.912,43.387 4.912,43.387 12.912,43.387 23.7,43.4 32.912,43.387 34.912,43.387 36.912,43.387 64.912,43.387 102.912,43.387 104.912,43.387 106.912,43.387 108.912,43.387 59,43.8 62.2,44 109.7,44.137 54.2,44.75 0.8,44.8 28.1,44.927 1.912,45.387 3.912,45.387 5.912,45.387 29.912,45.387 35.912,45.387 37.912,45.387 101.912,45.387 103.912,45.387 105.912,45.387 107.912,45.387 109.7,46.137 55.85,46.275 29.8,46.3 24.437,46.762 0.8,46.8 50.4,46.841 47.9,47.1 79.4,47.125 60.525,47.325 65.9,47.325 68.375,47.325 2.912,47.387 4.912,47.387 32.912,47.387 34.912,47.387 36.912,47.387 48.912,47.387 52.912,47.387 62.912,47.387 70.912,47.387 72.912,47.387 98.912,47.387 100.912,47.387 102.912,47.387 104.912,47.387 106.912,47.387 108.912,47.387 29.7,47.9 109.7,48.137 30.2,48.4 24.007,48.646 0.8,48.8 1.912,49.387 3.912,49.387 5.912,49.387 11.912,49.387 39.912,49.387 43.912,49.387 47.912,49.387 49.912,49.387 65.912,49.387 67.912,49.387 75.912,49.387 79.912,49.387 81.912,49.387 85.912,49.387 91.912,49.387 93.912,49.387 95.912,49.387 97.912,49.387 99.912,49.387 101.912,49.387 103.912,49.387 105.912,49.387 107.912,49.387 30.2,49.9 109.7,50.137 0.8,50.8 2.912,51.387 4.912,51.387 42.912,51.387 44.912,51.387 46.912,51.387 48.912,51.387 52.912,51.387 56.912,51.387 58.912,51.387 60.912,51.387 80.912,51.387 82.912,51.387 86.912,51.387 88.912,51.387 108.912,51.387 65.5,51.7 68.1,51.7 70.7,51.7 73.2,51.7 27.8,52 30.1,52 32.6,52.1 36.1,52.1 109.7,52.137 38.8,52.2 40.4,52.2 20.4,52.4 0.8,52.8 3.912,53.387 5.912,53.387 9.912,53.387 11.912,53.387 13.912,53.387 75.912,53.387 97.912,53.387 99.912,53.387 101.912,53.387 107.912,53.387 23.3,53.6 2.4,54.1 109.7,54.137 29.9,54.2 23.1,54.3 28,54.4 0.8,54.8 32.4,55.2 41.4,55.2 68.15,55.25 46.912,55.387 48.912,55.387 50.912,55.387 52.912,55.387 54.912,55.387 56.912,55.387 58.912,55.387 60.912,55.387 62.912,55.387 64.912,55.387 70.912,55.387 72.912,55.387 74.912,55.387 76.912,55.387 78.912,55.387 96.912,55.387 102.912,55.387 108.912,55.387 12.5,55.6 109.7,56.137 10.475,56.425 14.646,56.425 39.533,56.421 41.875,56.425 46.046,56.425 20.1,56.5 4.4,56.7 5.7,56.7 0.8,56.8 2.4,56.8 9.912,57.387 29.912,57.387 31.912,57.387 35.912,57.387 37.912,57.387 49.912,57.387 51.912,57.387 53.912,57.387 55.912,57.387 57.912,57.387 59.912,57.387 61.912,57.387 63.912,57.387 65.912,57.387 95.912,57.387 97.912,57.387 99.912,57.387 101.912,57.387 103.912,57.387 107.912,57.387 68.175,57.75 70.85,57.75 76.075,57.75 81.9,57.75 27.1,57.8 30.915,57.814 4.4,58 109.7,58.137 9.684,58.5 41.084,58.5 15.505,58.525 46.905,58.525 92.325,58.6 89.8,58.625 93.6,58.625 87.15,58.675 30.915,58.764 84.725,58.75 0.8,58.8 88.525,58.775 72.4,58.85 76.125,58.85 82.05,58.85 6.912,59.387 24.912,59.387 32.912,59.387 34.912,59.387 40.912,59.387 46.912,59.387 48.912,59.387 50.912,59.387 52.912,59.387 54.912,59.387 56.912,59.387 58.912,59.387 60.912,59.387 62.912,59.387 64.912,59.387 66.912,59.387 68.912,59.387 96.912,59.387 4.5,59.8 109.7,60.137 14.808,60.4 46.208,60.4 10.59,60.6 41.99,60.6 30.915,60.744 0.8,60.8 1.912,61.387 7.912,61.387 9.912,61.387 11.912,61.387 13.912,61.387 15.912,61.387 17.912,61.387 19.912,61.387 21.912,61.387 23.912,61.387 29.912,61.387 31.912,61.387 33.912,61.387 39.912,61.387 41.912,61.387 45.912,61.387 47.912,61.387 49.912,61.387 51.912,61.387 53.912,61.387 55.912,61.387 57.912,61.387 59.912,61.387 61.912,61.387 63.912,61.387 65.912,61.387 67.912,61.387 69.912,61.387 71.912,61.387 73.912,61.387 75.912,61.387 77.912,61.387 79.912,61.387 81.912,61.387 95.912,61.387 97.912,61.387 99.912,61.387 101.912,61.387 103.912,61.387 105.912,61.387 107.912,61.387 12.8,61.425 44.2,61.425 30.915,61.694 0.8,62.7 3.404,62.7 5.404,62.7 7.404,62.7 9.404,62.7 11.404,62.7 21.404,62.7 23.404,62.7 25.404,62.7 27.404,62.7 29.404,62.7 31.404,62.7 33.404,62.7 35.404,62.7 37.404,62.7 39.404,62.7 41.404,62.7 43.404,62.7 45.404,62.7 47.404,62.7 49.404,62.7 51.404,62.7 53.404,62.7 55.404,62.7 57.404,62.7 59.404,62.7 61.404,62.7 63.404,62.7 65.404,62.7 67.404,62.7 69.404,62.7 71.404,62.7 73.404,62.7 75.403,62.7 77.403,62.7 79.403,62.7 81.403,62.7 83.403,62.7 85.403,62.7 87.403,62.7 89.403,62.7 91.403,62.7 93.403,62.7 95.403,62.7 97.403,62.7 99.403,62.7 101.403,62.7 103.403,62.7 105.403,62.7 107.403,62.7
  other v2: 15.2,8.715 16.409,8.905 15.2,10.785 31.419,14.085 15.5,16.385 16.1,16.385
  other v3: 17.404,13.499 12.947,14.144 14.215,14.907 15.531,15.336 17.404,15.659 33.518,18.354 31.481,22.604 11.579,23.833 11.579,25.449 9.225,27.235 9.825,27.235 10.6,27.825
  other v4: 19.242,44.646 20.442,44.646 21.642,44.646 19.242,45.846 21.642,45.846 19.242,47.046 20.442,47.046 21.642,47.046
LED_PWR: C77.2 R19.2 R20.2 R21.2 R22.2 U10.31 | length 122.2
  Top Layer w0.25: U10.31@21.692,43.396 21.692,40.796 22.888,39.6 28.2,39.6 30.9,42.3 v1(30.9,55.805) ; R21.2@101.1,55.69 102.065,55.69 102.825,56.45 102.825,58.975 ; R19.2@101.1,58.99 102.81,58.99 102.825,58.975 ; v1(102.35,60.4) 102.358,60.408 102.817,60.408 C77.2@102.825,60.415 ; R22.2@107.362,55.69 108.327,55.69 109.087,56.45 109.087,59.968 108.64,60.415 C77.2@102.825,60.415 ; R20.2@107.362,58.99 109.072,58.99 ; 102.825,58.975 C77.2@102.825,60.415
  Mid-Layer 2 w0.25: v1(30.9,55.805) 30.948,55.757 46.504,55.757 51.01,60.263 ; 51.01,60.413 102.337,60.413 v1(102.35,60.4)
LED_PWR_CTRL: U2.A17 U10.8 | length 34.5
  Top Layer w0.125: U2.A17@22.46,19.064 22.46,19.287 22.693,19.519 22.693,22.288 22.852,22.447 23.347,22.447 24,23.1 25,23.1 v1(25.4,23.5) ; U10.8@22.892,47.596 22.9,47.604 v1(22.9,48.775)
  Bottom Layer w0.125: v1(22.9,48.775) 24,47.675 24.275,47.675 25.8,46.15 25.8,23.9 v1(25.4,23.5)
NetC7_2: C7.2 L2.2 L3.1 | length 0.9
  Top Layer w0.27: L2.2@102.934,35.73 C7.2@102.933,36.25
  Top Layer w0.3: L2.2@103,35.73 L3.1@103.37,35.73
NetC8_2: C8.2 L3.2 L4.1 | length 0.8
  Top Layer w0.3: 104.149,35.73 104.9,35.73
NetC13_2: C13.2 R1.1 U1.31 | length 1.7
  Top Layer w0.15: U1.31@101.505,35.33 102.193,35.33 102.363,35.159 102.363,35.144 102.363,35.129 102.569,34.923 102.569,34.866 102.841,34.594 R1.1@102.841,34.579
NetC27_2: C27.2 C57.2 FB4.1 L8.1 U10.1 | length 15.1
  Top Layer w0.15: U10.1@22.892,44.096 22.892,41.657 23.068,41.481 24.924,41.481
  Top Layer w0.75: C27.2@24.924,42.186 24.924,41.481 24.924,41.189 25.364,40.75 28.15,40.75 28.9,41.5 28.9,45.874 FB4.1@28.9,46.55
NetC32_2: C32.2 C33.1 U2.A27 U2.G31 | length 8.8
  Top Layer w0.15: C32.2@24.953,20.385 C32.2@25.032,20.306
  Top Layer w0.2: U2.A27@24.46,19.064 24.46,19.64 24.801,19.98 C32.2@24.801,20.381 ; C32.2@24.803,20.535 24.953,20.385 C32.2@24.953,20.34 ; C32.2@25.032,20.306 v1(25.512,20.306) ; U2.G31@25.46,17.664 27.185,17.664 27.409,17.889 27.409,18.056 27.444,18.091 C33.1@27.459,18.091 27.494,18.056 27.618,18.056 v1@27.884,17.79
  Bottom Layer w0.2: v1(25.512,20.306) 25.512,19.99 25.512,19.791 27.124,18.179 27.51,17.793 27.882,17.793 v1(27.885,17.79)
NetC39_2: C39.2 U2.A15 | length 2.8
  Top Layer w0.225: U2.A15@22.06,19.064 22.06,19.42 22.286,19.646 22.286,21.619 C39.2@22.151,21.754
NetC42_1: C42.1 R40.1 U2.A5 U2.E1 | length 7.8
  Top Layer w0.15: R40.1@16.469,21.14 R40.1@16.469,21.155 ; C42.1@17.226,20.947 17.867,20.306 19.391,20.306 20.06,19.637 U2.A5@20.06,19.064
  Top Layer w0.2: R40.1@16.469,21.14 16.657,20.952 C42.1@17.232,20.952 ; v1@18.577,18.152 18.966,18.152 19.054,18.064 U2.E1@19.06,18.064
  Bottom Layer w0.2: v1(18.575,18.15) 18.575,19.65 v1(19.275,20.35)
NetC43_1: C43.1 U2.B6 | length 4.1
  Top Layer w0.15: C43.1@18.4,20.952 19.348,20.952 20.31,19.99 20.391,19.909 20.391,18.938 ; U2.B6@20.26,18.664 20.391,18.934
  Top Layer w0.187: C43.1@18.4,20.952 C43.1@18.665,20.687
NetC44_1: C44.1 U2.A23 | length 1.1
  Top Layer w0.2: C44.1@23.551,20.154 23.551,20.139 23.66,20.029 U2.A23@23.66,19.064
